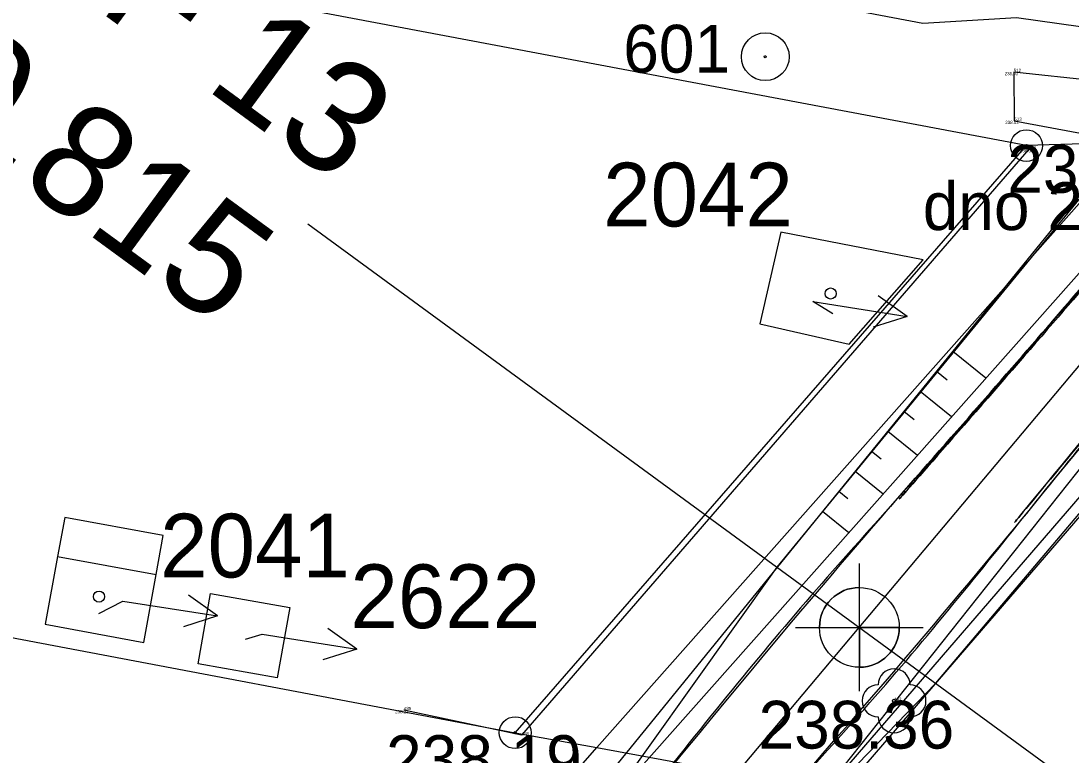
# Model space of a CAD drawing. Extents: x -555757 to -553364, y -1100723 to -1096439.
# Drawn here: x -554162.78 to -554129.85, y -1100104.12 to -1100081.09 of the extents above; entities that cross this region are included whole.
import ezdxf

# ---------------------------------------------------------------- set-up
doc = ezdxf.new("R2010")
doc.units = 0
for name, color, linetype in [('00_NÁVRH - 0.18 mm', 7, 'Continuous'), ('00_NÁVRH - 0.35 mm', 7, 'Continuous'), ('00_NÁVRH - Kóty výškové', 7, 'Continuous'), ('00_NÁVRH - Řezy', 7, 'Continuous'), ('01_HLADINA', 7, 'Continuous'), ('BUDOVY', 7, 'Continuous'), ('C$SLO$PARCELY', 7, 'Continuous'), ('Geodet. výšky - netisknuté', 7, 'Continuous'), ('HRANA$SVAHU', 7, 'Continuous'), ('HRANICE$PARCELY', 7, 'Continuous'), ('OSA$KOLEJI', 7, 'Continuous'), ('PLOTY', 7, 'Continuous'), ('POPIS', 7, 'Continuous'), ('ROZHRANI', 7, 'Continuous'), ('SLOUPY', 7, 'Continuous'), ('SLUCKOV$$C$RA', 7, 'Continuous'), ('STROMY', 7, 'Continuous'), ('VOZOVKA', 7, 'Continuous'), ('VSTUP', 7, 'Continuous'), ('VYSKA_PODR_BOD', 7, 'Continuous'), ('VYSKOVE$SRAFY', 7, 'Continuous')]:
    doc.layers.add(name, color=color, linetype=linetype)

# ---------------------------------------------------------------- blocks, each defined once
blk = doc.blocks.new('POINT_DISPLAY')
blk.add_line((0, 0), (0, 0))
blk = doc.blocks.new('4$02')
at = {"layer": 'SLOUPY'}
blk.add_circle((0, 0), 0.175, dxfattribs=at)
blk = doc.blocks.new('1029')
at = {"layer": 'PLOTY'}
for p, q in [((0, 0), (2.964, -0.468)), ((2.964, -0.468), (2.052, 0.182)), ((2.964, -0.468), (1.897, -0.807))]:
    blk.add_line(p, q, dxfattribs=at)
blk = doc.blocks.new('1$01')
at = {"layer": 'SLOUPY'}
for radius in [0.75, 0.032]:
    blk.add_circle((0, 0), radius, dxfattribs=at)
blk = doc.blocks.new('1$05')
at = {"layer": 'SLOUPY'}
for radius in [0.5, 0.032]:
    blk.add_circle((0, 0), radius, dxfattribs=at)
blk = doc.blocks.new('3$13')
at = {"layer": 'STROMY'}
blk.add_circle((0, 0), 0.05, dxfattribs=at)
for centre, start, end in [((0, 0.5), 0, 180), ((-0.5, 0), 90, 270), ((0.5, 0), 270, 90), ((0, -0.5), 180, 0)]:
    blk.add_arc(centre, 0.5, start, end, dxfattribs=at)
blk = doc.blocks.new('ZN_Výšková kóta - Půdorys')
for p, q in [((0, -2), (0, 2)), ((-2, 0), (2, 0))]:
    blk.add_line(p, q)
for points in [[(-1.25, 0), (0, 0), (0, 1.25)], [(1.25, 0), (0, 0), (0, -1.25)]]:
    blk.add_lwpolyline(points)
blk.add_circle((0, 0), 1.25)
for start, end in [(90, 180), (270, 0)]:
    blk.add_arc((0, 0), 1.25, start, end)

msp = doc.modelspace()

# ---------------------------------------------------------------- linework, layer by layer
at = {"layer": '00_NÁVRH - 0.18 mm'}
for points in [[(-554155.294, -1100122.105), (-554148.22, -1100114.565), (-554146.07, -1100111.389), (-554141.552, -1100106.146), (-554124.496, -1100085.83), (-554102.806, -1100062.713), (-554086.184, -1100036.979), (-554068.9, -1100012.208), (-554066.554, -1100010.303), (-554064.697, -1100008.795), (-554061.11, -1100004.288), (-554050.801, -1099985.182), (-554030.4, -1099954.846), (-554021.287, -1099939.518), (-554013.834, -1099925)], [(-554145.259, -1100106.49), (-554145.21, -1100106.43), (-554144.38, -1100105.67), (-554139.069, -1100098.226), (-554128.736, -1100085.64), (-554127.959, -1100084.912)], [(-554139.464, -1100107.587), (-554138.67, -1100106.61), (-554134.093, -1100101.871), (-554120.706, -1100086.029)]]:
    msp.add_lwpolyline(points, dxfattribs=at)
at = {"layer": '00_NÁVRH - 0.35 mm'}
for points in [[(-554140.321, -1100107.13), (-554135.037, -1100101.179), (-554129.948, -1100094.949), (-554124.652, -1100088.482), (-554122.98, -1100086.361), (-554122.484, -1100085.758), (-554137.678, -1100104.155), (-554122.734, -1100086.058)], [(-554144.178, -1100106.696), (-554137.941, -1100099.052), (-554133.547, -1100094.115), (-554128.427, -1100088.18), (-554125.854, -1100085.349), (-554141.103, -1100102.839), (-554127.159, -1100086.748)]]:
    msp.add_open_spline(points, degree=3, dxfattribs=at)
at = {"layer": '00_NÁVRH - Řezy'}
msp.add_line((-554153.783, -1100087.449), (-554127.684, -1100106.565), dxfattribs=at)
at = {"layer": '01_HLADINA'}
for points in [[(-554125.854, -1100085.349), (-554126.724, -1100086.282), (-554129.344, -1100089.155), (-554133.226, -1100093.851), (-554138.733, -1100099.803), (-554142.127, -1100104.123), (-554144.178, -1100106.696)], [(-554140.321, -1100107.13), (-554138.559, -1100105.147), (-554134.934, -1100101.228), (-554129.926, -1100094.831), (-554125.791, -1100089.986), (-554123.388, -1100086.853), (-554122.65, -1100085.958), (-554122.484, -1100085.758)]]:
    msp.add_open_spline(points, degree=3, dxfattribs=at)
at = {"layer": 'HRANA$SVAHU'}
for p, q in [((-554128.76, -1100085.54), (-554144.85, -1100105.34)), ((-554138.67, -1100106.61), (-554122.4, -1100086.09)), ((-554127.129, -1100086.206), (-554144.38, -1100105.67)), ((-554138.41, -1100106.88), (-554120.63, -1100086.25))]:
    msp.add_line(p, q, dxfattribs=at)
at = {"layer": 'HRANICE$PARCELY'}
for p, q in [((-554131.25, -1100085), (-554307.054, -1100051.702)), ((-554127.9, -1100084.89), (-554144.72, -1100103.89)), ((-554127.9, -1100084.89), (-554131.25, -1100085)), ((-554137.51, -1100105.21), (-554121.26, -1100086.38)), ((-554230.33, -1100087.72), (-554147.28, -1100103.42)), ((-554147.28, -1100103.42), (-554144.72, -1100103.89)), ((-554144.72, -1100103.89), (-554137.51, -1100105.21))]:
    msp.add_line(p, q, dxfattribs=at)
for points in [[(-554125.54, -1100081.84), (-554131.56, -1100080.99), (-554134.5, -1100081.17), (-554158.01, -1100076.71), (-554153.38, -1100056.06)], [(-554134.49, -1100088.58), (-554138.95, -1100087.72), (-554139.61, -1100090.59), (-554136.81, -1100091.23), (-554134.49, -1100088.58)], [(-554158.32, -1100097.23), (-554161.4, -1100096.67), (-554161.63, -1100097.89), (-554162.02, -1100100.02), (-554158.93, -1100100.59), (-554158.54, -1100098.46), (-554158.32, -1100097.23)], [(-554154.74, -1100101.7), (-554157.22, -1100101.26), (-554156.83, -1100099.05), (-554154.35, -1100099.49), (-554154.74, -1100101.7)]]:
    msp.add_lwpolyline(points, dxfattribs=at)
at = {"layer": 'PLOTY'}
for p, q in [((-554131.18, -1100085.11), (-554147.08, -1100103.5)), ((-554137.32, -1100090.28), (-554137.95, -1100089.89)), ((-554160.34, -1100099.68), (-554159.58, -1100099.29)), ((-554155.74, -1100100.49), (-554155.21, -1100100.33)), ((-554147.08, -1100103.5), (-554150.77, -1100102.71))]:
    msp.add_line(p, q, dxfattribs=at)
at = {"layer": 'SLUCKOV$$C$RA'}
for p, q in [((-554147.28, -1100103.42), (-554131.25, -1100085)), ((-554161.63, -1100097.89), (-554158.54, -1100098.46)), ((-554146.53, -1100105.94), (-554144.72, -1100103.89))]:
    msp.add_line(p, q, dxfattribs=at)
at = {"layer": 'VOZOVKA'}
for p, q in [((-554126.6, -1100083.23), (-554131.65, -1100082.69)), ((-554131.65, -1100082.69), (-554131.63, -1100084.22)), ((-554131.63, -1100084.22), (-554127.6, -1100084.98))]:
    msp.add_line(p, q, dxfattribs=at)
at = {"layer": 'VYSKOVE$SRAFY'}
for p, q in [((-554133.558, -1100091.445), (-554132.52, -1100092.289)), ((-554134.069, -1100092.073), (-554133.732, -1100092.347)), ((-554134.58, -1100092.702), (-554133.595, -1100093.502)), ((-554135.09, -1100093.33), (-554134.771, -1100093.589)), ((-554135.601, -1100093.958), (-554134.67, -1100094.714)), ((-554136.111, -1100094.586), (-554135.81, -1100094.831)), ((-554136.622, -1100095.215), (-554135.745, -1100095.927)), ((-554137.133, -1100095.843), (-554136.849, -1100096.073)), ((-554137.643, -1100096.471), (-554136.82, -1100097.14))]:
    msp.add_line(p, q, dxfattribs=at)

# ---------------------------------------------------------------- block references
at = {"layer": '00_NÁVRH - Kóty výškové'}
msp.add_blockref('ZN_Výšková kóta - Půdorys', (-554136.489, -1100100.116), dxfattribs=at)
at = {"layer": 'BUDOVY'}
for p in [(-554137.39, -1100089.64), (-554160.33, -1100099.15)]:
    msp.add_blockref('4$02', p, dxfattribs=at)
at = {"layer": 'PLOTY'}
for p in [(-554137.95, -1100089.89), (-554159.58, -1100099.29), (-554155.21, -1100100.33)]:
    msp.add_blockref('1029', p, dxfattribs=at)
at = {"layer": 'ROZHRANI'}
for p in [(-554131.65, -1100082.69), (-554131.63, -1100084.22), (-554131.18, -1100085.11), (-554135.4, -1100102.42), (-554150.77, -1100102.71), (-554147.08, -1100103.5)]:
    msp.add_blockref('POINT_DISPLAY', p, dxfattribs=at)
at = {"layer": 'STROMY'}
msp.add_blockref('3$13', (-554135.4, -1100102.42), dxfattribs=at)
at = {"layer": 'VSTUP'}
for name, p in [('1$01', (-554139.44, -1100082.21)), ('1$05', (-554131.25, -1100085)), ('1$05', (-554147.28, -1100103.42))]:
    msp.add_blockref(name, p, dxfattribs=at)

# ---------------------------------------------------------------- texts
at = {"layer": '00_NÁVRH - Řezy'}
for s, p in [('km 0,815', (-554172.147, -1100079.371)), ('PF 13', (-554162.931, -1100078.873))]:
    msp.add_text(s, height=3.5, rotation=323.7808, dxfattribs=at).set_placement(p)
at = {"layer": 'C$SLO$PARCELY'}
for s, p in [('2042', (-554144.523, -1100087.536)), ('2041', (-554158.413, -1100098.55)), ('2622', (-554152.448, -1100100.14))]:
    msp.add_text(s, height=2, dxfattribs=at).set_placement(p)
at = {"layer": 'Geodet. výšky - netisknuté'}
for s, p in [('238.03', (-554131.933, -1100082.79)), ('238.02', (-554131.913, -1100084.32)), ('238.01', (-554131.455, -1100085.21)), ('238.21', (-554151.045, -1100102.81))]:
    msp.add_text(s, height=0.1, dxfattribs=at).set_placement(p)
at = {"layer": 'OSA$KOLEJI'}
for s, p in [('512', (-554131.65, -1100082.69)), ('513', (-554131.63, -1100084.22)), ('514', (-554131.18, -1100085.11)), ('485', (-554150.77, -1100102.71)), ('492', (-554135.4, -1100102.42)), ('498', (-554147.08, -1100103.5))]:
    msp.add_text(s, height=0.1, dxfattribs=at).set_placement(p)
at = {"layer": 'POPIS'}
msp.add_text('dno 236.78', height=1.5, dxfattribs=at).set_placement((-554134.5, -1100087.649))
at = {"layer": 'VSTUP'}
msp.add_text('601', height=1.5, dxfattribs=at).set_placement((-554143.892, -1100082.71))
at = {"layer": 'VYSKA_PODR_BOD'}
for s, p in [('237.87', (-554131.85, -1100086.48)), ('238.36', (-554139.65, -1100103.92)), ('238.19', (-554151.33, -1100105))]:
    msp.add_text(s, height=1.5, dxfattribs=at).set_placement(p)

doc.saveas('drawing.dxf')
